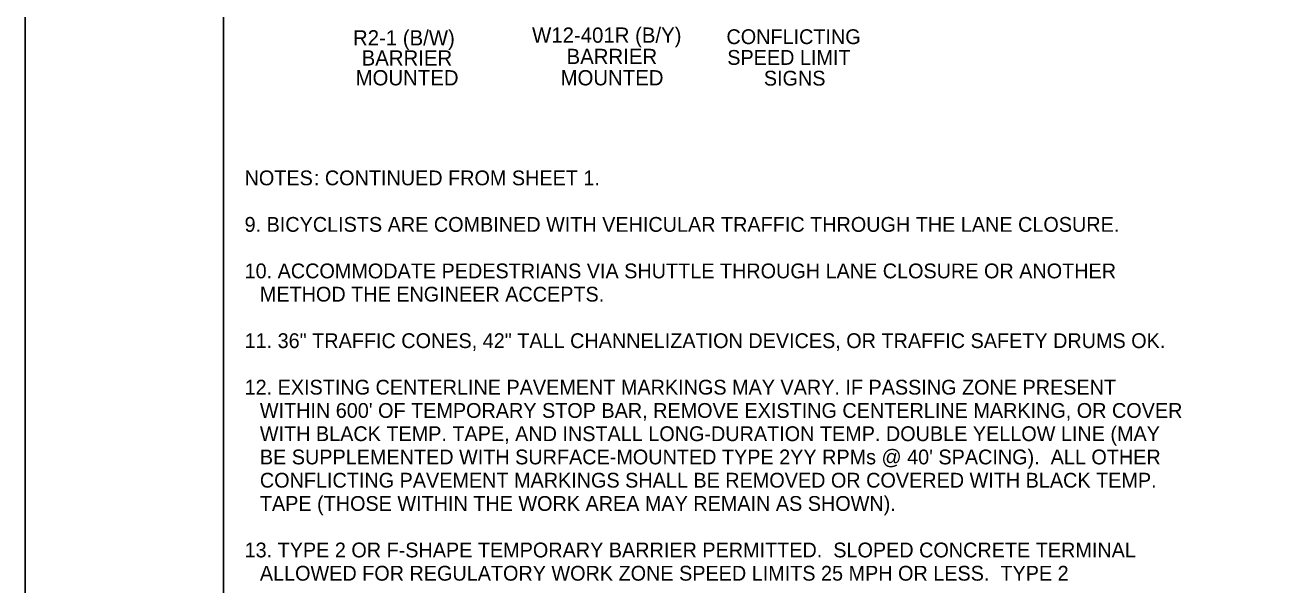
# Model space of a CAD drawing. Extents: x 99982 to 100176, y 99905 to 100011.
# Drawn here: x 100019.06 to 100025, y 99942.89 to 99945.53 of the extents above; entities that cross this region are included whole.
import ezdxf

# ---------------------------------------------------------------- set-up
doc = ezdxf.new("R2010")
doc.units = 0
for name, color, linetype in [('SH_GI_GeneralNotesBodyText', 7, 'Continuous'), ('SH_GI_PlotLimits', 7, 'Continuous'), ('SH_GI_SheetBorder', 7, 'Continuous'), ('TR_SN_ConstructionSigns', 7, 'Continuous')]:
    doc.layers.add(name, color=color, linetype=linetype)

msp = doc.modelspace()

# ---------------------------------------------------------------- linework, layer by layer
at = {"layer": 'SH_GI_PlotLimits'}
msp.add_lwpolyline([(100019.0625, 99939.6875), (100036.0625, 99939.6875), (100036.0625, 99950.6875), (100019.0625, 99950.6875)], close=True, dxfattribs=at)
at = {"layer": 'SH_GI_SheetBorder'}
msp.add_line((100020, 99950.375), (100020, 99940), dxfattribs=at)

# ---------------------------------------------------------------- texts
at = {"layer": 'SH_GI_GeneralNotesBodyText'}
for s, p in [('NOTES', (100020.1, 99944.778)), (': CONTINUED FROM SHEET 1.', (100020.4275, 99944.778)), ('9. BICYCLISTS ARE COMBINED WITH VEHICULAR TRAFFIC THROUGH THE LANE CLOSURE.', (100020.1, 99944.5582)), ('10. ACCOMMODATE PEDESTRIANS VIA SHUTTLE THROUGH LANE CLOSURE OR ANOTHER ', (100020.1, 99944.3384)), ('METHOD THE ENGINEER ACCEPTS.', (100020.1722, 99944.2285)), ('11. 36" TRAFFIC CONES, 42" TALL CHANNELIZATION DEVICES, OR TRAFFIC SAFETY DRUMS OK.', (100020.1, 99944.0087)), ('12. EXISTING CENTERLINE PAVEMENT MARKINGS MAY VARY. IF PASSING ZONE PRESENT ', (100020.1, 99943.7889)), ("WITHIN 600' OF TEMPORARY STOP BAR, REMOVE EXISTING CENTERLINE MARKING, OR COVER ", (100020.1722, 99943.679)), ('WITH BLACK TEMP. TAPE, AND INSTALL LONG-DURATION TEMP. DOUBLE YELLOW LINE (MAY ', (100020.1722, 99943.5691)), ("BE SUPPLEMENTED WITH SURFACE-MOUNTED TYPE 2YY RPMs @ 40' SPACING).  ALL OTHER ", (100020.1722, 99943.4592)), ('CONFLICTING PAVEMENT MARKINGS SHALL BE REMOVED OR COVERED WITH BLACK TEMP. ', (100020.1722, 99943.3493)), ('TAPE (THOSE WITHIN THE WORK AREA MAY REMAIN AS SHOWN).', (100020.1722, 99943.2394)), ('13. TYPE 2 OR F-SHAPE TEMPORARY BARRIER PERMITTED.  SLOPED CONCRETE TERMINAL ', (100020.1, 99943.0196)), ('ALLOWED FOR REGULATORY WORK ZONE SPEED LIMITS 25 MPH OR LESS.  TYPE 2 ', (100020.1722, 99942.9097))]:
    msp.add_text(s, height=0.07, rotation=360, dxfattribs=at).set_placement(p)
at = {"layer": 'TR_SN_ConstructionSigns'}
for s, p in [('R2-1 (B/W)', (100020.6124, 99945.439)), ('W12-401R (B/Y)', (100021.4589, 99945.4518)), ('BARRIER', (100020.6533, 99945.3439)), ('BARRIER', (100021.6221, 99945.351)), ('MOUNTED', (100020.6247, 99945.2502)), ('MOUNTED', (100021.5935, 99945.2502))]:
    msp.add_text(s, height=0.072, rotation=360, dxfattribs=at).set_placement(p)
for s, p in [('CONFLICTING', (100022.3778, 99945.4452)), ('SPEED LIMIT', (100022.3816, 99945.3472)), ('SIGNS', (100022.5546, 99945.2492))]:
    msp.add_text(s, height=0.07, dxfattribs=at).set_placement(p)

doc.saveas('drawing.dxf')
